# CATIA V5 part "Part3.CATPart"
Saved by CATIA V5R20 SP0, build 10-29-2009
Part number: Part3
Bounding box of the stored display mesh (mm): x -0.48 to 0.48, y -0.1 to 0.1, z -0.48 to 0.48
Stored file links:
  C:\Users\scupi\Desktop\Product\Part3.CATPart
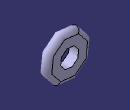
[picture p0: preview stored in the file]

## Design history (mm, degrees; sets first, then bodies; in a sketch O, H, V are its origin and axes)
Body1 (main body)
  DatumCurve1
  Plane1: stored without definition
  Sketch1 on yz-plane, origin (0, 0, 0), H (0, 1, 0), V (0, 0, 1)
    line L1 (-0.1, 0.2) -> (0.1, 0.2)
    line L2 (0.1, 0.2) -> (0.1, 0.4)
    line L3 (-0.1, 0.4) -> (-0.1, 0.2)
    arc A1 centre (0, 0.4) radius 0.1 from (0.1, 0.4) to (-0.1, 0.4) ccw
    point P5 (0, 0.4)
    point P6 (-0.1, 0.4)
    axis line L4 (1.1003, 0) -> (-1.1112, 0)
    point P7 (1.1003, 0)
    distance L2 V = 0.1
    distance L3 L2 = 0.2
    distance H L1 = 0.2
    distance P5 H = 0.4
    radius A1 = 0.1
    horizontal: L1 H, L4 H
    vertical: L2 V, L3 V
    tangency: A1 L3
    coincidence: A1 P6, P7 H
  Shaft1: profile Sketch1, axis Sketch1.L4, angle 360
